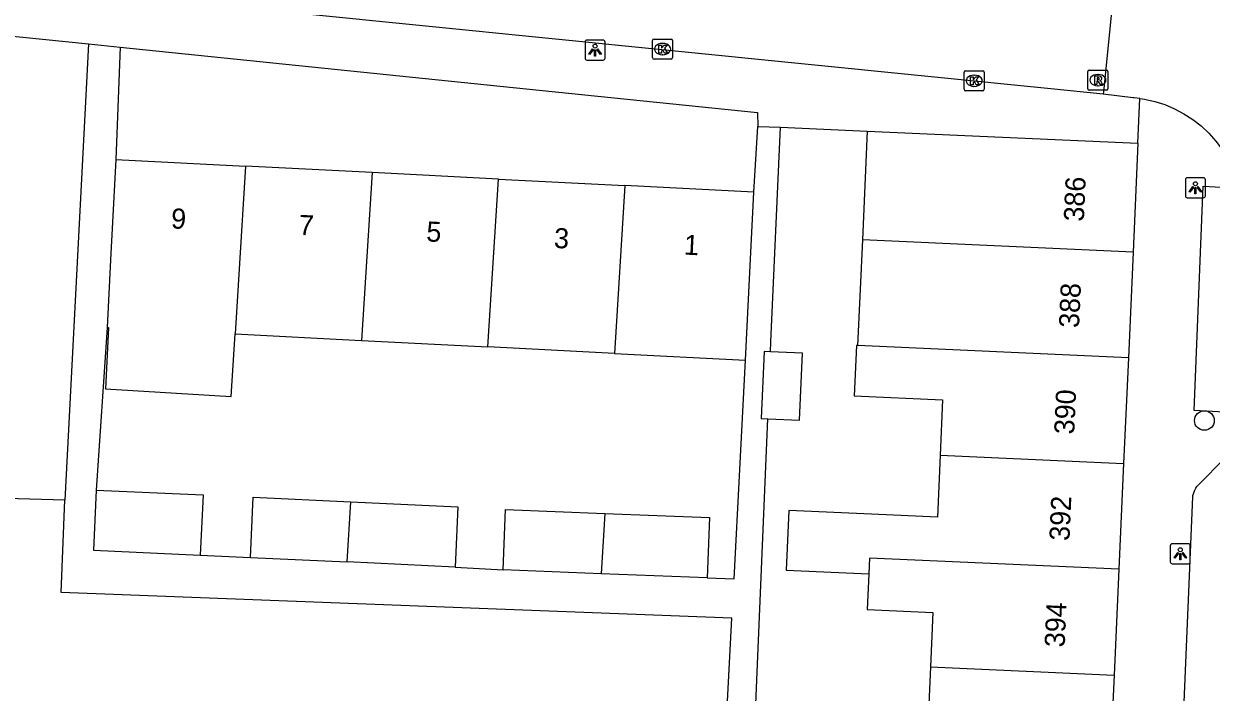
# Model space of a CAD drawing. Extents: x 161253 to 161848, y 384872 to 385383.
# Drawn here: x 161590.4 to 161649.5, y 384970 to 385003.2 of the extents above; entities that cross this region are included whole.
import ezdxf

# ---------------------------------------------------------------- set-up
doc = ezdxf.new("R2010")
doc.units = 0
for name, color, linetype in [('IMGEO_Boom', 7, 'Continuous'), ('IMGEO_Groenvoorziening', 7, 'Continuous'), ('IMGEO_Kolk', 7, 'Continuous'), ('IMGEO_Lichtpunt', 7, 'Continuous'), ('IMGEO_Pand', 7, 'Continuous'), ('IMGEO_Pand_nummerreeks', 7, 'Continuous'), ('IMGEO_Rijbaan_lokaal_open', 7, 'Continuous'), ('IMGEO_Rioolput', 7, 'Continuous'), ('IMGEO_Voetpad_open', 7, 'Continuous')]:
    doc.layers.add(name, color=color, linetype=linetype)

msp = doc.modelspace()

# ---------------------------------------------------------------- linework, layer by layer
at = {"layer": 'IMGEO_Boom'}
msp.add_circle((161649.152, 384983.483), 0.489, dxfattribs=at)
at = {"layer": 'IMGEO_Groenvoorziening'}
msp.add_lwpolyline([(161592.462, 384979.511), (161587.199, 384979.67), (161588.066, 385002.802)], dxfattribs=at)
at = {"layer": 'IMGEO_Kolk'}
for p, q in [((161621.699, 385001.549), (161621.699, 385002.401)), ((161621.774, 385002.475), (161622.626, 385002.475)), ((161622.187, 385002.255), (161622.212, 385002.255)), ((161622.7, 385002.401), (161622.7, 385001.549)), ((161622.626, 385001.475), (161621.774, 385001.475)), ((161622.21, 385001.695), (161622.185, 385001.695)), ((161637.2, 384999.971), (161637.2, 385000.823)), ((161637.275, 385000.897), (161638.127, 385000.897)), ((161638.201, 385000.823), (161638.201, 384999.971)), ((161637.688, 385000.677), (161637.713, 385000.677)), ((161638.127, 384999.897), (161637.275, 384999.897)), ((161637.711, 385000.117), (161637.686, 385000.117))]:
    msp.add_line(p, q, dxfattribs=at)
for points in [[(161621.699, 385001.549), (161621.699, 385002.401)], [(161621.774, 385002.475), (161622.626, 385002.475)], [(161622.02, 385002.175), (161622.143, 385002.175), (161622.143, 385002.024), (161622.273, 385002.175), (161622.437, 385002.175), (161622.291, 385002.024), (161622.444, 385001.775), (161622.292, 385001.775), (161622.207, 385001.939), (161622.143, 385001.872), (161622.143, 385001.775), (161622.02, 385001.775), (161622.02, 385002.175)], [(161622.7, 385002.401), (161622.7, 385001.549)], [(161622.626, 385001.475), (161621.774, 385001.475)], [(161637.2, 384999.971), (161637.2, 385000.823)], [(161637.275, 385000.897), (161638.127, 385000.897)], [(161638.201, 385000.823), (161638.201, 384999.971)], [(161637.521, 385000.597), (161637.644, 385000.597), (161637.644, 385000.446), (161637.774, 385000.597), (161637.938, 385000.597), (161637.792, 385000.446), (161637.945, 385000.197), (161637.793, 385000.197), (161637.708, 385000.361), (161637.644, 385000.294), (161637.644, 385000.197), (161637.521, 385000.197), (161637.521, 385000.597)], [(161638.127, 384999.897), (161637.275, 384999.897)]]:
    msp.add_lwpolyline(points, dxfattribs=at)
for centre, start, end in [((161621.776, 385002.399), 91.55205, 178.44795), ((161621.776, 385002.399), 91.55205, 178.44795), ((161622.624, 385002.399), 1.55205, 88.44795), ((161622.624, 385002.399), 1.55205, 88.44795), ((161621.776, 385001.551), 181.55205, 268.44795), ((161621.776, 385001.551), 181.55205, 268.44795), ((161622.624, 385001.551), 271.55205, 358.44795), ((161622.624, 385001.551), 271.55205, 358.44795), ((161637.277, 385000.821), 91.55205, 178.44795), ((161637.277, 385000.821), 91.55205, 178.44795), ((161638.125, 385000.821), 1.55205, 88.44795), ((161638.125, 385000.821), 1.55205, 88.44795), ((161637.277, 384999.973), 181.55205, 268.44795), ((161637.277, 384999.973), 181.55205, 268.44795), ((161638.125, 384999.973), 271.55205, 358.44795), ((161638.125, 384999.973), 271.55205, 358.44795)]:
    msp.add_arc(centre, 0.0765, start, end, dxfattribs=at)
for centre, major_axis, ratio, start_param, end_param in [((161622.186, 385001.975), (-0.387, 0.002), 0.722429, 4.712389, 7.853982), ((161622.211, 385001.975), (-0.39, 0.002), 0.717154, 1.570796, 4.712389), ((161637.687, 385000.397), (-0.387, 0.002), 0.722429, 4.712389, 7.853982), ((161637.712, 385000.397), (-0.39, 0.002), 0.717154, 1.570796, 4.712389)]:
    msp.add_ellipse(centre, major_axis=major_axis, ratio=ratio, start_param=start_param, end_param=end_param, dxfattribs=at)
at = {"layer": 'IMGEO_Lichtpunt'}
for p, q in [((161618.343, 385002.326), (161618.343, 385001.519)), ((161618.343, 385002.326), (161618.343, 385001.519)), ((161619.245, 385002.421), (161618.437, 385002.421)), ((161619.245, 385002.421), (161618.437, 385002.421)), ((161619.339, 385001.519), (161619.339, 385002.326)), ((161619.339, 385001.519), (161619.339, 385002.326)), ((161618.437, 385001.425), (161619.245, 385001.425)), ((161618.437, 385001.425), (161619.245, 385001.425)), ((161648.208, 384995.472), (161648.208, 384994.665)), ((161648.208, 384995.472), (161648.208, 384994.665)), ((161649.11, 384995.567), (161648.302, 384995.567)), ((161649.11, 384995.567), (161648.302, 384995.567)), ((161649.204, 384994.665), (161649.204, 384995.472)), ((161649.204, 384994.665), (161649.204, 384995.472)), ((161648.302, 384994.571), (161649.11, 384994.571)), ((161648.302, 384994.571), (161649.11, 384994.571)), ((161647.454, 384977.251), (161647.454, 384976.444)), ((161647.454, 384977.251), (161647.454, 384976.444)), ((161648.356, 384977.346), (161647.548, 384977.346)), ((161648.356, 384977.346), (161647.548, 384977.346)), ((161648.45, 384976.444), (161648.45, 384977.251)), ((161648.45, 384976.444), (161648.45, 384977.251)), ((161647.548, 384976.35), (161648.356, 384976.35)), ((161647.548, 384976.35), (161648.356, 384976.35))]:
    msp.add_line(p, q, dxfattribs=at)
for points in [[(161618.717, 385001.99), (161618.756, 385001.962), (161618.568, 385001.7), (161618.53, 385001.727), (161618.717, 385001.99)], [(161618.819, 385001.942), (161618.866, 385001.942), (161618.866, 385001.62), (161618.819, 385001.62), (161618.819, 385001.942)], [(161618.929, 385001.962), (161618.967, 385001.989), (161619.154, 385001.727), (161619.115, 385001.699), (161618.929, 385001.962)], [(161648.582, 384995.136), (161648.621, 384995.108), (161648.433, 384994.846), (161648.395, 384994.873), (161648.582, 384995.136)], [(161648.684, 384995.088), (161648.731, 384995.088), (161648.731, 384994.766), (161648.684, 384994.766), (161648.684, 384995.088)], [(161648.794, 384995.108), (161648.832, 384995.135), (161649.019, 384994.873), (161648.98, 384994.845), (161648.794, 384995.108)], [(161647.828, 384976.915), (161647.867, 384976.887), (161647.679, 384976.625), (161647.641, 384976.652), (161647.828, 384976.915)], [(161647.93, 384976.867), (161647.977, 384976.867), (161647.977, 384976.545), (161647.93, 384976.545), (161647.93, 384976.867)], [(161648.04, 384976.887), (161648.078, 384976.914), (161648.265, 384976.652), (161648.226, 384976.624), (161648.04, 384976.887)]]:
    msp.add_lwpolyline(points, dxfattribs=at)
for centre in [(161618.842, 385002.124), (161648.707, 384995.27), (161647.953, 384977.049)]:
    msp.add_circle(centre, 0.0994, dxfattribs=at)
for centre, start, end in [((161618.437, 385002.326), 90, 180), ((161618.437, 385002.326), 90, 180), ((161619.245, 385002.326), 0, 90), ((161619.245, 385002.326), 0, 90), ((161618.437, 385001.519), 180, 270), ((161618.437, 385001.519), 180, 270), ((161619.245, 385001.519), 270, 0), ((161619.245, 385001.519), 270, 360), ((161648.302, 384995.472), 90, 180), ((161648.302, 384995.472), 90, 180), ((161649.11, 384995.472), 0, 90), ((161649.11, 384995.472), 0, 90), ((161648.302, 384994.665), 180, 270), ((161648.302, 384994.665), 180, 270), ((161649.11, 384994.665), 270, 0), ((161649.11, 384994.665), 270, 360), ((161647.548, 384977.251), 90, 180), ((161647.548, 384977.251), 90, 180), ((161648.356, 384977.251), 0, 90), ((161648.356, 384977.251), 0, 90), ((161647.548, 384976.444), 180, 270), ((161647.548, 384976.444), 180, 270), ((161648.356, 384976.444), 270, 0), ((161648.356, 384976.444), 270, 360)]:
    msp.add_arc(centre, 0.0946, start, end, dxfattribs=at)
at = {"layer": 'IMGEO_Pand'}
for points in [[(161632.383, 384997.891), (161632.14, 384992.477)], [(161632.383, 384997.891), (161645.849, 384997.285)], [(161645.849, 384997.285), (161645.605, 384991.87)], [(161594.998, 384996.476), (161594.742, 384991.483), (161594.57, 384988.118)], [(161594.998, 384996.476), (161601.449, 384996.146)], [(161601.449, 384996.146), (161600.929, 384987.792)], [(161607.748, 384995.822), (161601.449, 384996.146)], [(161607.748, 384995.822), (161607.213, 384987.47)], [(161614.037, 384995.501), (161607.748, 384995.822)], [(161613.508, 384987.148), (161614.037, 384995.501)], [(161614.037, 384995.501), (161620.317, 384995.179)], [(161620.317, 384995.179), (161619.813, 384986.825)], [(161626.744, 384994.851), (161620.317, 384995.179)], [(161626.316, 384986.492), (161626.488, 384989.858), (161626.744, 384994.851)], [(161632.14, 384992.477), (161631.903, 384987.211)], [(161645.605, 384991.87), (161632.14, 384992.477)], [(161645.605, 384991.87), (161645.369, 384986.605)], [(161594.57, 384988.118), (161594.637, 384988.115), (161594.48, 384985.061), (161600.735, 384984.672), (161600.929, 384987.792)], [(161600.929, 384987.792), (161607.213, 384987.47)], [(161607.213, 384987.47), (161613.508, 384987.148)], [(161631.903, 384987.211), (161631.839, 384987.214), (161631.726, 384984.711), (161636.13, 384984.513), (161636.006, 384981.751)], [(161645.369, 384986.605), (161631.903, 384987.211)], [(161619.813, 384986.825), (161613.508, 384987.148)], [(161619.813, 384986.825), (161626.316, 384986.492)], [(161627.57, 384986.903), (161627.26, 384986.917), (161627.11, 384983.586), (161627.432, 384983.572)], [(161627.432, 384983.572), (161629.006, 384983.501), (161629.156, 384986.831), (161627.57, 384986.903)], [(161645.369, 384986.605), (161645.132, 384981.34)], [(161636.006, 384981.751), (161635.867, 384978.667), (161632.59, 384978.815), (161628.482, 384979.001), (161628.348, 384976.035), (161632.457, 384975.85)], [(161636.006, 384981.751), (161645.132, 384981.34)], [(161645.132, 384981.34), (161644.895, 384976.076)], [(161594.028, 384980.021), (161593.89, 384977.022), (161599.197, 384976.776)], [(161594.028, 384980.021), (161599.336, 384979.775), (161599.197, 384976.776)], [(161601.698, 384976.661), (161601.837, 384979.66), (161606.698, 384979.435)], [(161606.506, 384976.439), (161606.698, 384979.435)], [(161606.698, 384979.435), (161612.015, 384979.189), (161611.876, 384976.19)], [(161614.261, 384976.046), (161614.379, 384979.05), (161619.332, 384978.855)], [(161619.332, 384978.855), (161619.151, 384975.854)], [(161619.332, 384978.855), (161624.536, 384978.651), (161624.418, 384975.647)], [(161601.698, 384976.661), (161606.506, 384976.439)], [(161644.895, 384976.076), (161632.492, 384976.634), (161632.457, 384975.85)], [(161611.876, 384976.19), (161606.506, 384976.439)], [(161619.151, 384975.854), (161614.261, 384976.046)], [(161644.895, 384976.076), (161644.658, 384970.811)], [(161624.418, 384975.647), (161619.151, 384975.854)], [(161632.457, 384975.85), (161632.376, 384974.072), (161635.644, 384973.925), (161635.522, 384971.222)], [(161635.522, 384971.222), (161635.388, 384968.233), (161632.133, 384968.379)], [(161635.522, 384971.222), (161644.658, 384970.811)], [(161644.658, 384970.811), (161644.421, 384965.546)]]:
    msp.add_lwpolyline(points, dxfattribs=at)
at = {"layer": 'IMGEO_Rijbaan_lokaal_open'}
for points in [[(161644.123, 384999.737), (161641.51, 385000), (161585.261, 385005.661), (161583.856, 385005.737), (161582.451, 385005.688), (161581.055, 385005.513), (161579.681, 385005.214), (161579.302, 385005.109), (161561.812, 385000), (161542.1, 384994.163), (161525.218, 384989.124)], [(161644.619, 385004.674), (161644.15, 385000), (161644.123, 384999.737)], [(161645.935, 384999.514), (161645.656, 384999.55), (161645.614, 384999.554), (161644.123, 384999.737)], [(161645.935, 384999.514), (161646.177, 384999.482), (161646.689, 384999.368), (161647.189, 384999.208), (161647.673, 384999.004), (161648.136, 384998.758), (161648.576, 384998.472), (161648.989, 384998.147), (161649.371, 384997.787), (161649.719, 384997.394), (161650.03, 384996.972), (161650.303, 384996.523), (161650.534, 384996.052), (161650.723, 384995.562), (161650.867, 384995.058)]]:
    msp.add_lwpolyline(points, dxfattribs=at)
at = {"layer": 'IMGEO_Rioolput'}
for p, q in [((161643.353, 385000.003), (161643.353, 385000.855)), ((161643.428, 385000.929), (161644.28, 385000.929)), ((161644.354, 385000.855), (161644.354, 385000.003)), ((161643.841, 385000.709), (161643.866, 385000.709)), ((161644.28, 384999.929), (161643.428, 384999.929)), ((161643.864, 385000.149), (161643.839, 385000.149))]:
    msp.add_line(p, q, dxfattribs=at)
for points in [[(161643.353, 385000.003), (161643.353, 385000.855)], [(161643.428, 385000.929), (161644.28, 385000.929)], [(161644.354, 385000.855), (161644.354, 385000.003)], [(161643.942, 385000.627), (161643.69, 385000.629), (161643.69, 385000.229)], [(161643.69, 385000.229), (161643.814, 385000.229), (161643.814, 385000.391), (161643.825, 385000.391)], [(161643.868, 385000.548), (161643.814, 385000.548), (161643.814, 385000.467)], [(161643.814, 385000.467), (161643.866, 385000.467)], [(161643.872, 385000.362), (161643.943, 385000.229), (161644.083, 385000.229), (161644.018, 385000.355)], [(161644.28, 384999.929), (161643.428, 384999.929)]]:
    msp.add_lwpolyline(points, dxfattribs=at)
for centre, radius, start, end in [((161643.43, 385000.853), 0.0765, 91.55205, 178.44795), ((161643.43, 385000.853), 0.0765, 91.55205, 178.44795), ((161644.278, 385000.853), 0.0765, 1.55205, 88.44795), ((161644.278, 385000.853), 0.0765, 1.55205, 88.44795), ((161643.824, 385000.338), 0.0533, 26.02933, 88.69889), ((161643.85, 385000.656), 0.19, 274.7715, 282.96867), ((161643.874, 385000.452), 0.0964, 77.00612, 93.18647), ((161643.888, 385000.509), 0.0378, 276.66336, 79.67722), ((161643.941, 385000.517), 0.109, 350.36119, 89.41601), ((161643.939, 385000.517), 0.112, 277.58423, 350.98172), ((161643.923, 385000.302), 0.108, 29.51342, 73.79051), ((161643.43, 385000.005), 0.0765, 181.55205, 268.44795), ((161643.43, 385000.005), 0.0765, 181.55205, 268.44795), ((161644.278, 385000.005), 0.0765, 271.55205, 358.44795), ((161644.278, 385000.005), 0.0765, 271.55205, 358.44795)]:
    msp.add_arc(centre, radius, start, end, dxfattribs=at)
for centre, major_axis, ratio, start_param, end_param in [((161643.84, 385000.429), (-0.387, 0.002), 0.722429, 4.712389, 7.853982), ((161643.865, 385000.429), (-0.39, 0.002), 0.717154, 1.570796, 4.712389)]:
    msp.add_ellipse(centre, major_axis=major_axis, ratio=ratio, start_param=start_param, end_param=end_param, dxfattribs=at)
at = {"layer": 'IMGEO_Voetpad_open'}
for points in [[(161588.066, 385002.802), (161593.647, 385002.23)], [(161593.647, 385002.23), (161592.462, 384979.511)], [(161593.647, 385002.23), (161595.212, 385002.07)], [(161595.212, 385002.07), (161594.998, 384996.476)], [(161595.212, 385002.07), (161615.406, 385000), (161626.928, 384998.819), (161626.939, 384998.127)], [(161645.849, 384997.285), (161645.935, 384999.514)], [(161626.744, 384994.851), (161626.939, 384998.127)], [(161626.939, 384998.127), (161628.071, 384998.085)], [(161627.57, 384986.903), (161627.591, 384987.405), (161628.071, 384998.085)], [(161628.071, 384998.085), (161632.383, 384997.891)], [(161650.732, 384983.873), (161648.636, 384983.986), (161649.084, 384995.146), (161650.867, 384995.058)], [(161594.57, 384988.118), (161594.028, 384980.021)], [(161624.418, 384975.647), (161625.754, 384975.594), (161626.316, 384986.492)], [(161626.22, 384955.8), (161626.356, 384958.33), (161626.711, 384966.22), (161627.432, 384983.572)], [(161647.607, 384956.463), (161648.571, 384979.678), (161648.582, 384979.742), (161648.606, 384979.838), (161648.638, 384979.932), (161648.678, 384980.022), (161648.727, 384980.108), (161648.782, 384980.19), (161648.845, 384980.266), (161648.915, 384980.336), (161650.124, 384981.559), (161650.236, 384981.669), (161650.338, 384981.789), (161650.428, 384981.917), (161650.507, 384982.053), (161650.573, 384982.195), (161650.627, 384982.343), (161650.666, 384982.495), (161650.687, 384982.606)], [(161626.25, 384936.206), (161625.759, 384936.226), (161626.147, 384945.126), (161625.827, 384949.231), (161624.614, 384953.921), (161625.652, 384973.647), (161592.287, 384974.913), (161592.462, 384979.511)], [(161599.197, 384976.776), (161601.698, 384976.661)], [(161611.876, 384976.19), (161614.261, 384976.046)]]:
    msp.add_lwpolyline(points, dxfattribs=at)

# ---------------------------------------------------------------- texts
at = {"layer": 'IMGEO_Pand_nummerreeks'}
for s, rotation, p in [('386', 87.4219, (161643.152, 384993.373)), ('9', 357.07219, (161597.73, 384993.052)), ('7', 357.06973, (161604.08, 384992.727)), ('5', 357.06973, (161610.429, 384992.402)), ('3', 357.06973, (161616.778, 384992.077)), ('1', 357.06973, (161623.241, 384991.746)), ('388', 87.4219, (161642.913, 384988.078)), ('390', 87.4219, (161642.675, 384982.779)), ('392', 87.4219, (161642.436, 384977.475)), ('394', 87.4219, (161642.198, 384972.179))]:
    msp.add_text(s, height=1, rotation=rotation, dxfattribs=at).set_placement(p)

doc.saveas('drawing.dxf')
